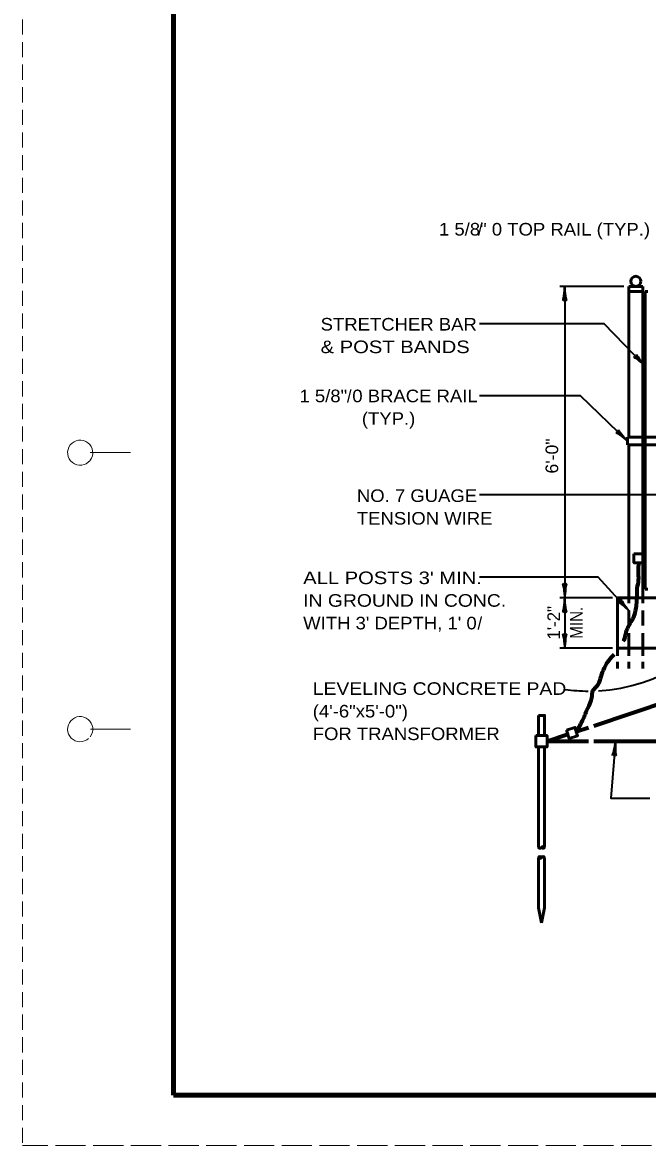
# Model space of a CAD drawing. Extents: x -1 to 679, y 0 to 440.
# Drawn here: x -1.5 to 122.8, y -0.1 to 223.4 of the extents above; entities that cross this region are included whole.
import ezdxf
from ezdxf.enums import TextEntityAlignment as Align

# ---------------------------------------------------------------- set-up
doc = ezdxf.new("R2010")
doc.units = 0
for name, pattern in [('LONG_DASHED', [7.5, 6, -1.5]), ('MEDIUM_DASHED', [4.5, 3, -1.5]), ('SHORT_DASHED', [2.7, 1.5, -1.2])]:
    doc.linetypes.add(name, pattern=pattern)
doc.layers.add('1', color=7, linetype='Continuous', lineweight=53)
doc.layers.add('61', color=7, linetype='Continuous', lineweight=35)

msp = doc.modelspace()

# ---------------------------------------------------------------- linework, layer by layer
at = {"layer": '1', "linetype": 'MEDIUM_DASHED', "lineweight": 13}
msp.add_line((-1.431, 439.961), (-1.491, -0.079), dxfattribs=at)
at = {"layer": '1', "lineweight": 35}
for p, q in [((118.099, 170.858), (105.349, 170.858)), ((115.849, 108.858), (105.349, 108.858)), ((115.849, 98.858), (105.349, 98.858))]:
    msp.add_line(p, q, dxfattribs=at)
at = {"layer": '1'}
for p, q in [((119.099, 170.858), (121.849, 170.858)), ((119.099, 140.858), (119.099, 170.858)), ((119.099, 169.858), (121.849, 169.858)), ((121.849, 140.858), (121.849, 170.858)), ((122.349, 140.858), (122.349, 169.858)), ((122.349, 169.858), (122.849, 169.858)), ((118.849, 140.858), (118.849, 139.358)), ((118.849, 140.858), (204.947, 140.858)), ((118.849, 139.358), (204.947, 139.358)), ((119.099, 108.858), (119.099, 139.358)), ((121.849, 139.608), (121.849, 140.608)), ((121.849, 108.858), (121.849, 139.358)), ((122.349, 139.608), (122.349, 140.608)), ((122.349, 110.608), (122.349, 139.358)), ((122.349, 110.608), (122.849, 110.608)), ((116.849, 98.858), (116.849, 108.858)), ((116.849, 108.858), (138.849, 108.858)), ((116.849, 98.858), (160.099, 98.858)), ((101.099, 81.483), (101.099, 85.483)), ((101.099, 79.233), (101.099, 59.233)), ((102.349, 79.233), (102.349, 59.233)), ((101.099, 57.233), (101.099, 47.233)), ((102.349, 57.233), (102.349, 47.233)), ((101.099, 47.233), (101.724, 44.233)), ((102.349, 47.233), (101.724, 44.233))]:
    msp.add_line(p, q, dxfattribs=at)
at = {"layer": '1', "linetype": 'MEDIUM_DASHED'}
for p, q in [((119.099, 98.858), (119.099, 108.858)), ((121.849, 98.858), (121.849, 108.858))]:
    msp.add_line(p, q, dxfattribs=at)
at = {"layer": '1', "linetype": 'SHORT_DASHED'}
for p, q in [((116.849, 98.858), (116.849, 94.858)), ((119.099, 98.858), (119.099, 94.858)), ((121.849, 98.858), (121.849, 94.858))]:
    msp.add_line(p, q, dxfattribs=at)
at = {"layer": '1', "lineweight": 70}
for p, q in [((112.099, 83.449), (127.099, 88.462)), ((108.634, 82.291), (111.099, 83.115)), ((102.849, 80.358), (106.974, 81.736)), ((102.849, 80.358), (111.099, 80.358)), ((112.099, 80.358), (127.099, 80.358))]:
    msp.add_line(p, q, dxfattribs=at)
at = {"layer": '1', "lineweight": 35}
for points in [[(106.349, 170.858), (106.349, 108.858), (106.349, 98.858)], [(122.349, 154.993), (114.154, 163.384), (89.42, 163.384)], [(118.849, 140.05), (109.455, 149.087), (89.42, 149.087)], [(131.779, 111.358), (126.431, 129.402), (89.42, 129.402)], [(119.099, 106.298), (113.012, 113.005), (89.42, 113.005)], [(116.441, 80.358), (115.517, 69.054), (123.261, 69.054)]]:
    msp.add_lwpolyline(points, dxfattribs=at)
at = {"layer": '1'}
for points in [[(120.1, 117.609), (121.85, 117.608), (121.849, 115.858), (120.099, 115.858)], [(106.697, 82.566), (108.357, 83.121), (108.911, 81.461), (107.252, 80.906)], [(100.599, 81.483), (102.849, 81.483), (102.849, 79.233), (100.599, 79.233)]]:
    msp.add_lwpolyline(points, close=True, dxfattribs=at)
msp.add_lwpolyline([(102.349, 81.483), (102.349, 85.483), (101.099, 85.483)], dxfattribs=at)
msp.add_circle((120.474, 171.858), 1, dxfattribs=at)
at = {"layer": '1', "lineweight": 35}
for start, end in [(273.19613, 333.34814), (261.86999, 269.7196)]:
    msp.add_arc((111.196, 123.928), 33.596, start, end, dxfattribs=at)
at = {"layer": '1'}
for centre, start, end in [((101.412, 59.413), 209.9406, 330.0594), ((102.037, 59.053), 29.9406, 150.0594), ((102.037, 59.413), 209.9406, 330.0594), ((101.412, 57.053), 29.9406, 150.0594), ((101.412, 57.413), 209.9406, 330.0594), ((102.037, 57.053), 29.9406, 150.0594)]:
    msp.add_arc(centre, 0.361, start, end, dxfattribs=at)
at = {"layer": '1', "lineweight": 40}
for centre, major_axis, ratio, start_param, end_param in [((106.138, 169.737), (0.176, 1.756), 0.07063, 3.1407148, 5.41811), ((106.138, 169.737), (0.176, 1.756), 0.07063, 3.1407148, 5.41811), ((106.626, 169.766), (-0.156, 1.786), 0.122415, 0.8963533, 3.1415927), ((106.626, 169.766), (-0.156, 1.786), 0.122415, 0.8963533, 3.1415927), ((121.389, 155.58), (1.359, -1.168), 0.122415, 0.8963533, 3.1415927), ((121.389, 155.58), (1.359, -1.168), 0.122415, 0.8963533, 3.1415927), ((121.718, 155.942), (-1.102, 1.379), 0.07063, 6.2823074, 8.5597026), ((121.718, 155.942), (-1.102, 1.379), 0.07063, 6.2823074, 8.5597026), ((117.871, 140.608), (1.395, -1.125), 0.122415, 0.8963533, 3.1415927), ((118.188, 140.98), (-1.144, 1.344), 0.07063, 6.2823074, 8.5597026), ((106.073, 109.949), (0.156, -1.786), 0.122415, 0.8963533, 3.1415927), ((106.073, 109.949), (0.156, -1.786), 0.122415, 0.8963533, 3.1415927), ((106.561, 109.978), (-0.176, -1.756), 0.07063, 3.1407148, 5.41811), ((106.561, 109.978), (-0.176, -1.756), 0.07063, 3.1407148, 5.41811), ((106.138, 107.737), (0.176, 1.756), 0.07063, 3.1407148, 5.41811), ((106.626, 107.766), (-0.156, 1.786), 0.122415, 0.8963533, 3.1415927), ((118.161, 106.921), (1.316, -1.217), 0.122415, 0.8963533, 3.1415927), ((118.503, 107.27), (-1.05, 1.419), 0.07063, 6.2823074, 8.5597026), ((106.073, 99.949), (0.156, -1.786), 0.122415, 0.8963533, 3.1415927), ((106.561, 99.978), (-0.176, -1.756), 0.07063, 3.1407148, 5.41811), ((116.139, 79.258), (-0.318, -1.736), 0.07063, 6.2823074, 8.5597026), ((116.628, 79.248), (-0.01, 1.792), 0.122415, 0.8963533, 3.1415927)]:
    msp.add_ellipse(centre, major_axis=major_axis, ratio=ratio, start_param=start_param, end_param=end_param, dxfattribs=at)
at = {"layer": '1', "lineweight": 70}
for points in [[(121.077, 115.877), (120.921, 114.27), (120.973, 112.404), (120.714, 110.797), (120.662, 109.294), (120.455, 106.755), (119.989, 104.993), (119.833, 104.682), (119.16, 103.541), (118.693, 102.557), (118.331, 101.468), (118.175, 100.691), (117.968, 100.224)], [(108.634, 82.291), (110.041, 84.78), (110.922, 86.905), (111.751, 88.978), (111.958, 90.429), (112.994, 91.621), (113.564, 93.228), (114.238, 94.938), (115.17, 96.493), (116.155, 97.581)]]:
    msp.add_spline(points, degree=3, dxfattribs=at)
at = {"layer": '61', "lineweight": 13}
for p, q in [((11.989, 137.781), (19.989, 137.781)), ((12.009, 82.761), (19.989, 82.761))]:
    msp.add_line(p, q, dxfattribs=at)
at = {"layer": '61', "lineweight": 158}
msp.add_line((667.629, 9.921), (28.569, 9.941), dxfattribs=at)
at = {"layer": '61', "linetype": 'LONG_DASHED', "lineweight": 13}
msp.add_line((678.569, -0.059), (-1.491, -0.079), dxfattribs=at)
at = {"layer": '61', "lineweight": 158}
msp.add_lwpolyline([(667.609, 429.961), (28.569, 429.961), (28.569, 9.941)], dxfattribs=at)
at = {"layer": '61', "lineweight": 13}
for centre, start, end in [((9.987, 137.762), 322.67175, 321.71615), ((9.987, 82.762), 323.13009, 312.31439)]:
    msp.add_arc(centre, 2.5, start, end, dxfattribs=at)

# ---------------------------------------------------------------- texts
at = {"layer": '1', "width": 1.1}
for s, p in [('1 5/8" 0 TOP RAIL (TYP.)', (102.322, 180.97)), ('1 5/8" 0 BRACE RAIL', (71.314, 147.806)), ('(TYP.)', (71.314, 143.306))]:
    msp.add_text(s, height=2.5, dxfattribs=at).set_placement(p, align=Align.CENTER)
at = {"layer": '1'}
for p in [(89.543, 180.97), (63.487, 147.744), (89.46, 102.568)]:
    msp.add_text('/', height=2.5, dxfattribs=at).set_placement(p, align=Align.CENTER)
for s, width, p in [('STRETCHER BAR', 1.1, (57.805, 162.068)), ('& POST BANDS', 1.2, (57.805, 157.568)), ('NO. 7 GUAGE', 1.1, (65.01, 127.96)), ('TENSION WIRE', 1.1, (65.01, 123.46)), ("ALL POSTS 3' MIN.", 1.2, (54.331, 111.615)), ('IN GROUND IN CONC.', 1.15, (54.331, 107.115)), ("WITH 3' DEPTH, 1' 0", 1.1, (54.331, 102.615)), ('LEVELING CONCRETE PAD', 1.15, (56.233, 89.583)), ('(4\'-6"x5\'-0")', 1.1, (56.233, 85.083)), ('FOR TRANSFORMER', 1.1, (56.233, 80.583))]:
    msp.add_text(s, height=2.5, dxfattribs=dict(at, width=width)).set_placement(p)
for s, width, p in [('6\'-0"', 1.05, (105.035, 137.108)), ('MIN.', 0.9, (109.889, 103.93))]:
    msp.add_text(s, height=2.5, rotation=90, dxfattribs=dict(at, width=width)).set_placement(p, align=Align.CENTER)
msp.add_text('1\'-2"', height=2.5, rotation=90, dxfattribs=at).set_placement((105.389, 103.93), align=Align.CENTER)

doc.saveas('drawing.dxf')
